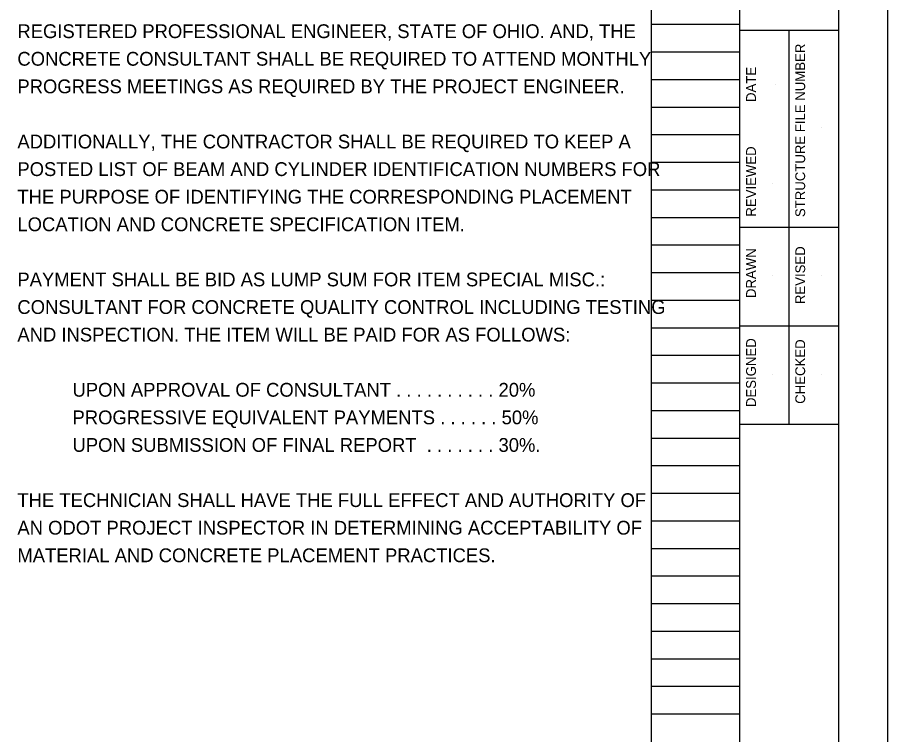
# Model space of a CAD drawing. Extents: x -14.8 to 34, y 0 to 43.2.
# Drawn here: x 25.16 to 34, y 10.85 to 18.13 of the extents above; entities that cross this region are included whole.
import ezdxf

# ---------------------------------------------------------------- set-up
doc = ezdxf.new("R2010")
doc.units = 0
for name, color, linetype in [('SH_Border', 7, 'Continuous'), ('SH_Cut_Line', 7, 'Continuous'), ('SH_Data', 7, 'Continuous'), ('SH_Text', 7, 'Continuous')]:
    doc.layers.add(name, color=color, linetype=linetype)

msp = doc.modelspace()

# ---------------------------------------------------------------- linework, layer by layer
at = {"layer": 'SH_Border'}
for p, q in [((32.5, 0.5), (32.5, 21.5)), ((32.5, 18), (33.5, 18)), ((33, 14), (33, 18)), ((32.5, 16), (33.5, 16)), ((32.5, 15), (33.5, 15)), ((32.5, 14), (33.5, 14))]:
    msp.add_line(p, q, dxfattribs=at)
msp.add_lwpolyline([(2, 21.5), (33.5, 21.5), (33.5, 0.5), (2, 0.5)], close=True, dxfattribs=at)
at = {"layer": 'SH_Cut_Line'}
msp.add_lwpolyline([(0, 22), (34, 22), (34, 0), (0, 0)], close=True, dxfattribs=at)
at = {"layer": 'SH_Data'}
for p, q in [((31.6, 0.98), (31.6, 21.14)), ((32.5, 0.98), (32.5, 21.14)), ((31.6, 18.06), (32.5, 18.06)), ((31.6, 17.78), (32.5, 17.78)), ((31.6, 17.5), (32.5, 17.5)), ((32.8596, 17.4493), (32.8596, 17.4493)), ((31.6, 17.22), (32.5, 17.22)), ((33.3333, 17.009), (33.3333, 17.009)), ((31.6, 16.94), (32.5, 16.94)), ((31.6, 16.66), (32.5, 16.66)), ((32.8333, 16.4474), (32.8333, 16.4474)), ((31.6, 16.38), (32.5, 16.38)), ((31.6, 16.1), (32.5, 16.1)), ((31.6, 15.82), (32.5, 15.82)), ((31.6, 15.54), (32.5, 15.54)), ((32.8333, 15.5099), (32.8333, 15.5099)), ((33.3333, 15.5099), (33.3333, 15.5099)), ((31.6, 15.26), (32.5, 15.26)), ((31.6, 14.98), (32.5, 14.98)), ((31.6, 14.7), (32.5, 14.7)), ((32.8333, 14.5099), (32.8333, 14.5099)), ((33.3333, 14.509), (33.3333, 14.509)), ((31.6, 14.42), (32.5, 14.42)), ((31.6, 14.14), (32.5, 14.14)), ((31.6, 13.86), (32.5, 13.86)), ((31.6, 13.58), (32.5, 13.58)), ((31.6, 13.3), (32.5, 13.3)), ((31.6, 13.02), (32.5, 13.02)), ((31.6, 12.74), (32.5, 12.74)), ((31.6, 12.46), (32.5, 12.46)), ((31.6, 12.18), (32.5, 12.18)), ((31.6, 11.9), (32.5, 11.9)), ((31.6, 11.62), (32.5, 11.62)), ((31.6, 11.34), (32.5, 11.34)), ((31.6, 11.06), (32.5, 11.06))]:
    msp.add_line(p, q, dxfattribs=at)

# ---------------------------------------------------------------- texts
for s, p in [('STRUCTURE FILE NUMBER', (33.1625, 16.1033)), ('DATE', (32.6625, 17.2715)), ('REVIEWED', (32.6625, 16.1076)), ('DRAWN', (32.6625, 15.2811)), ('REVISED', (33.1625, 15.2197)), ('DESIGNED', (32.6625, 14.1749)), ('CHECKED', (33.1625, 14.2079))]:
    msp.add_text(s, height=0.1, rotation=90, dxfattribs=at).set_placement(p)
at = {"layer": 'SH_Text'}
for s, p in [('REGISTERED PROFESSIONAL ENGINEER, STATE OF OHIO. AND, THE ', (25.16, 17.92)), ('CONCRETE CONSULTANT SHALL BE REQUIRED TO ATTEND MONTHLY ', (25.16, 17.64)), ('PROGRESS MEETINGS AS REQUIRED BY THE PROJECT ENGINEER.', (25.16, 17.36)), ('ADDITIONALLY, THE CONTRACTOR SHALL BE REQUIRED TO KEEP A ', (25.16, 16.8)), ('POSTED LIST OF BEAM AND CYLINDER IDENTIFICATION NUMBERS FOR ', (25.16, 16.52)), ('THE PURPOSE OF IDENTIFYING THE CORRESPONDING PLACEMENT ', (25.16, 16.24)), ('LOCATION AND CONCRETE SPECIFICATION ITEM.', (25.16, 15.96)), ('PAYMENT SHALL BE BID AS LUMP SUM FOR ITEM SPECIAL MISC.:  ', (25.16, 15.4)), ('CONSULTANT FOR CONCRETE QUALITY CONTROL INCLUDING TESTING ', (25.16, 15.12)), ('AND INSPECTION. THE ITEM WILL BE PAID FOR AS FOLLOWS:', (25.16, 14.84)), ('UPON APPROVAL OF CONSULTANT . . . . . . . . . . 20%', (25.72, 14.28)), ('PROGRESSIVE EQUIVALENT PAYMENTS . . . . . . 50%', (25.72, 14)), ('UPON SUBMISSION OF FINAL REPORT  . . . . . . . 30%.', (25.72, 13.72)), ('THE TECHNICIAN SHALL HAVE THE FULL EFFECT AND AUTHORITY OF ', (25.16, 13.16)), ('AN ODOT PROJECT INSPECTOR IN DETERMINING ACCEPTABILITY OF ', (25.16, 12.88)), ('MATERIAL AND CONCRETE PLACEMENT PRACTICES.', (25.16, 12.6))]:
    msp.add_text(s, height=0.14, dxfattribs=at).set_placement(p)

doc.saveas('drawing.dxf')
